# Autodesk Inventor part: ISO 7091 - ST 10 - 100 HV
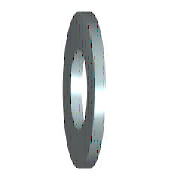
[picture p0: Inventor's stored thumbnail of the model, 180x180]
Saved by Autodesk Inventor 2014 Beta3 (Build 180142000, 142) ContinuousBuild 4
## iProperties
IsCustomPart: 0
Created: 2010-11
Part Number: ISO 7091 - ST 10 - 100 HV
Material: Steel
Description: Plain washers - Normal series - Product grade C
Document SubType Name: Modeling
Standard: ISO 7091
Designer: Thom Tremblay
Standard Revision: Second edition 2000-06-01
Standards Organization: ISO
Language: en-US
Size Designation: ST 10 - 100 HV
Categories: <MemberInstance><Categories><Category DisplayName="Fasteners" InternalName="e4da775c-781d-43d5-af7c-5136215cf5a6" Mnemonic="FSTN"><Category DisplayName="Washers
Density: 7.85 g/cm^3
Appearance: Steel
Author: Thom Tremblay
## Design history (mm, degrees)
sketch "Sketch"
  geometry: C1 r 10 at (0, 0); C2 r 5.5 at (0, 0); 1 further point
  constraints: 2 centre point, 2 coincident
  dimensions: "d0" = 11 diameter of C2 (= SD1); "d1" = 20 diameter of C1 (= SD2)
extrude "Body" new body sketch "Sketch" distance "d2" = 2 (= SD); taper "d3" = 0 deg
workaxis "Work Axis1"
workplane "Work Plane1"
body "Solid1"
other parameters: "SD1" = 11 [user parameter; used in 1 equation term], "SD2" = 20 [user parameter; used in 1 equation term], "SD" = 2 [user parameter; used in 1 equation term], "d4" = 0, "d5" = 0, "d6" = 0, "d7" = 0
